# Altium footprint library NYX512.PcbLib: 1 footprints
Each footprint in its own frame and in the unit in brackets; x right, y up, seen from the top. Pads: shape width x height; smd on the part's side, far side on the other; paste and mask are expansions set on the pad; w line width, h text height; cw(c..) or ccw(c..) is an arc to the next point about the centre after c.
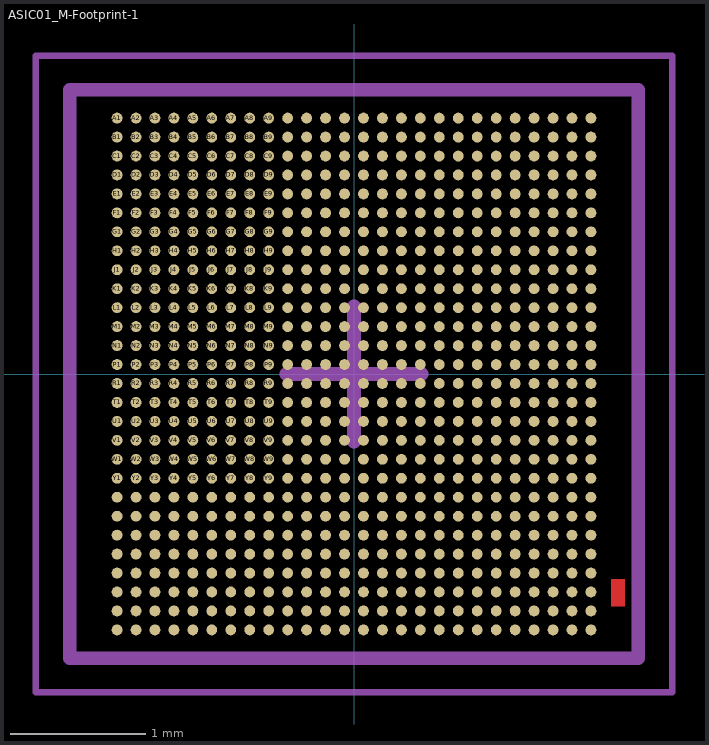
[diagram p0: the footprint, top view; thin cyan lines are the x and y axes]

## ASIC01_M-Footprint-1 [mm]
pads (728):
  round 0.08 smd mask+0: A1(-1.75,1.89) A2(-1.61,1.89) A3(-1.47,1.89) A4(-1.33,1.89) A5(-1.19,1.89) A6(-1.05,1.89) A7(-0.91,1.89) A8(-0.77,1.89) A9(-0.63,1.89) A10(-0.49,1.89) A11(-0.35,1.89) A12(-0.21,1.89) A13(-0.07,1.89) A14(0.07,1.89) A15(0.21,1.89) A16(0.35,1.89) A17(0.49,1.89) A18(0.63,1.89) A19(0.77,1.89) A20(0.91,1.89) A21(1.05,1.89) A22(1.19,1.89) A23(1.33,1.89) A24(1.47,1.89) A25(1.61,1.89) A26(1.75,1.89) AA1(-1.75,-0.91) AA2(-1.61,-0.91) AA3(-1.47,-0.91) AA4(-1.33,-0.91) AA5(-1.19,-0.91) AA6(-1.05,-0.91) AA7(-0.91,-0.91) AA8(-0.77,-0.91) AA9(-0.63,-0.91) AA10(-0.49,-0.91) AA11(-0.35,-0.91) AA12(-0.21,-0.91) AA13(-0.07,-0.91) AA14(0.07,-0.91) AA15(0.21,-0.91) AA16(0.35,-0.91) AA17(0.49,-0.91) AA18(0.63,-0.91) AA19(0.77,-0.91) AA20(0.91,-0.91) AA21(1.05,-0.91) AA22(1.19,-0.91) AA23(1.33,-0.91) AA24(1.47,-0.91) AA25(1.61,-0.91) AA26(1.75,-0.91) AB1(-1.75,-1.05) AB2(-1.61,-1.05) AB3(-1.47,-1.05) AB4(-1.33,-1.05) AB5(-1.19,-1.05) AB6(-1.05,-1.05) AB7(-0.91,-1.05) AB8(-0.77,-1.05) AB9(-0.63,-1.05) AB10(-0.49,-1.05) AB11(-0.35,-1.05) AB12(-0.21,-1.05) AB13(-0.07,-1.05) AB14(0.07,-1.05) AB15(0.21,-1.05) AB16(0.35,-1.05) AB17(0.49,-1.05) AB18(0.63,-1.05) AB19(0.77,-1.05) AB20(0.91,-1.05) AB21(1.05,-1.05) AB22(1.19,-1.05) AB23(1.33,-1.05) AB24(1.47,-1.05) AB25(1.61,-1.05) AB26(1.75,-1.05) AC1(-1.75,-1.19) AC2(-1.61,-1.19) AC3(-1.47,-1.19) AC4(-1.33,-1.19) AC5(-1.19,-1.19) AC6(-1.05,-1.19) AC7(-0.91,-1.19) AC8(-0.77,-1.19) AC9(-0.63,-1.19) AC10(-0.49,-1.19) AC11(-0.35,-1.19) AC12(-0.21,-1.19) AC13(-0.07,-1.19) AC14(0.07,-1.19) AC15(0.21,-1.19) AC16(0.35,-1.19) AC17(0.49,-1.19) AC18(0.63,-1.19) AC19(0.77,-1.19) AC20(0.91,-1.19) AC21(1.05,-1.19) AC22(1.19,-1.19) AC23(1.33,-1.19) AC24(1.47,-1.19) AC25(1.61,-1.19) AC26(1.75,-1.19) AD1(-1.75,-1.33) AD2(-1.61,-1.33) AD3(-1.47,-1.33) AD4(-1.33,-1.33) AD5(-1.19,-1.33) AD6(-1.05,-1.33) AD7(-0.91,-1.33) AD8(-0.77,-1.33) AD9(-0.63,-1.33) AD10(-0.49,-1.33) AD11(-0.35,-1.33) AD12(-0.21,-1.33) AD13(-0.07,-1.33) AD14(0.07,-1.33) AD15(0.21,-1.33) AD16(0.35,-1.33) AD17(0.49,-1.33) AD18(0.63,-1.33) AD19(0.77,-1.33) AD20(0.91,-1.33) AD21(1.05,-1.33) AD22(1.19,-1.33) AD23(1.33,-1.33) AD24(1.47,-1.33) AD25(1.61,-1.33) AD26(1.75,-1.33) AE1(-1.75,-1.47) AE2(-1.61,-1.47) AE3(-1.47,-1.47) AE4(-1.33,-1.47) AE5(-1.19,-1.47) AE6(-1.05,-1.47) AE7(-0.91,-1.47) AE8(-0.77,-1.47) AE9(-0.63,-1.47) AE10(-0.49,-1.47) AE11(-0.35,-1.47) AE12(-0.21,-1.47) AE13(-0.07,-1.47) AE14(0.07,-1.47) AE15(0.21,-1.47) AE16(0.35,-1.47) AE17(0.49,-1.47) AE18(0.63,-1.47) AE19(0.77,-1.47) AE20(0.91,-1.47) AE21(1.05,-1.47) AE22(1.19,-1.47) AE23(1.33,-1.47) AE24(1.47,-1.47) AE25(1.61,-1.47) AE26(1.75,-1.47) AF1(-1.75,-1.61) AF2(-1.61,-1.61) AF3(-1.47,-1.61) AF4(-1.33,-1.61) AF5(-1.19,-1.61) AF6(-1.05,-1.61) AF7(-0.91,-1.61) AF8(-0.77,-1.61) AF9(-0.63,-1.61) AF10(-0.49,-1.61) AF11(-0.35,-1.61) AF12(-0.21,-1.61) AF13(-0.07,-1.61) AF14(0.07,-1.61) AF15(0.21,-1.61) AF16(0.35,-1.61) AF17(0.49,-1.61) AF18(0.63,-1.61) AF19(0.77,-1.61) AF20(0.91,-1.61) AF21(1.05,-1.61) AF22(1.19,-1.61) AF23(1.33,-1.61) AF24(1.47,-1.61) AF25(1.61,-1.61) AF26(1.75,-1.61) AG1(-1.75,-1.75) AG2(-1.61,-1.75) AG3(-1.47,-1.75) AG4(-1.33,-1.75) AG5(-1.19,-1.75) AG6(-1.05,-1.75) AG7(-0.91,-1.75) AG8(-0.77,-1.75) AG9(-0.63,-1.75) AG10(-0.49,-1.75) AG11(-0.35,-1.75) AG12(-0.21,-1.75) AG13(-0.07,-1.75) AG14(0.07,-1.75) AG15(0.21,-1.75) AG16(0.35,-1.75) AG17(0.49,-1.75) AG18(0.63,-1.75) AG19(0.77,-1.75) AG20(0.91,-1.75) AG21(1.05,-1.75) AG22(1.19,-1.75) AG23(1.33,-1.75) AG24(1.47,-1.75) AG25(1.61,-1.75) AG26(1.75,-1.75) AH1(-1.75,-1.89) AH2(-1.61,-1.89) AH3(-1.47,-1.89) AH4(-1.33,-1.89) AH5(-1.19,-1.89) AH6(-1.05,-1.89) AH7(-0.91,-1.89) AH8(-0.77,-1.89) AH9(-0.63,-1.89) AH10(-0.49,-1.89) AH11(-0.35,-1.89) AH12(-0.21,-1.89) AH13(-0.07,-1.89) AH14(0.07,-1.89) AH15(0.21,-1.89) AH16(0.35,-1.89) AH17(0.49,-1.89) AH18(0.63,-1.89) AH19(0.77,-1.89) AH20(0.91,-1.89) AH21(1.05,-1.89) AH22(1.19,-1.89) AH23(1.33,-1.89) AH24(1.47,-1.89) AH25(1.61,-1.89) AH26(1.75,-1.89) B1(-1.75,1.75) B2(-1.61,1.75) B3(-1.47,1.75) B4(-1.33,1.75) B5(-1.19,1.75) B6(-1.05,1.75) B7(-0.91,1.75) B8(-0.77,1.75) B9(-0.63,1.75) B10(-0.49,1.75) B11(-0.35,1.75) B12(-0.21,1.75) B13(-0.07,1.75) B14(0.07,1.75) B15(0.21,1.75) B16(0.35,1.75) B17(0.49,1.75) B18(0.63,1.75) B19(0.77,1.75) B20(0.91,1.75) B21(1.05,1.75) B22(1.19,1.75) B23(1.33,1.75) B24(1.47,1.75) B25(1.61,1.75) B26(1.75,1.75) C1(-1.75,1.61) C2(-1.61,1.61) C3(-1.47,1.61) C4(-1.33,1.61) C5(-1.19,1.61) C6(-1.05,1.61) C7(-0.91,1.61) C8(-0.77,1.61) C9(-0.63,1.61) C10(-0.49,1.61) C11(-0.35,1.61) C12(-0.21,1.61) C13(-0.07,1.61) C14(0.07,1.61) C15(0.21,1.61) C16(0.35,1.61) C17(0.49,1.61) C18(0.63,1.61) C19(0.77,1.61) C20(0.91,1.61) C21(1.05,1.61) C22(1.19,1.61) C23(1.33,1.61) C24(1.47,1.61) C25(1.61,1.61) C26(1.75,1.61) D1(-1.75,1.47) D2(-1.61,1.47) D3(-1.47,1.47) D4(-1.33,1.47) D5(-1.19,1.47) D6(-1.05,1.47) D7(-0.91,1.47) D8(-0.77,1.47) D9(-0.63,1.47) D10(-0.49,1.47) D11(-0.35,1.47) D12(-0.21,1.47) D13(-0.07,1.47) D14(0.07,1.47) D15(0.21,1.47) D16(0.35,1.47) D17(0.49,1.47) D18(0.63,1.47) D19(0.77,1.47) D20(0.91,1.47) D21(1.05,1.47) D22(1.19,1.47) D23(1.33,1.47) D24(1.47,1.47) D25(1.61,1.47) D26(1.75,1.47) E1(-1.75,1.33) E2(-1.61,1.33) E3(-1.47,1.33) E4(-1.33,1.33) E5(-1.19,1.33) E6(-1.05,1.33) E7(-0.91,1.33) E8(-0.77,1.33) E9(-0.63,1.33) E10(-0.49,1.33) E11(-0.35,1.33) E12(-0.21,1.33) E13(-0.07,1.33) E14(0.07,1.33) E15(0.21,1.33) E16(0.35,1.33) E17(0.49,1.33) E18(0.63,1.33) E19(0.77,1.33) E20(0.91,1.33) E21(1.05,1.33) E22(1.19,1.33) E23(1.33,1.33) E24(1.47,1.33) E25(1.61,1.33) E26(1.75,1.33) F1(-1.75,1.19) F2(-1.61,1.19) F3(-1.47,1.19) F4(-1.33,1.19) F5(-1.19,1.19) F6(-1.05,1.19) F7(-0.91,1.19) F8(-0.77,1.19) F9(-0.63,1.19) F10(-0.49,1.19) F11(-0.35,1.19) F12(-0.21,1.19) F13(-0.07,1.19) F14(0.07,1.19) F15(0.21,1.19) F16(0.35,1.19) F17(0.49,1.19) F18(0.63,1.19) F19(0.77,1.19) F20(0.91,1.19) F21(1.05,1.19) F22(1.19,1.19) F23(1.33,1.19) F24(1.47,1.19) F25(1.61,1.19) F26(1.75,1.19) G1(-1.75,1.05) G2(-1.61,1.05) G3(-1.47,1.05) G4(-1.33,1.05) G5(-1.19,1.05) G6(-1.05,1.05) G7(-0.91,1.05) G8(-0.77,1.05) G9(-0.63,1.05) G10(-0.49,1.05) G11(-0.35,1.05) G12(-0.21,1.05) G13(-0.07,1.05) G14(0.07,1.05) G15(0.21,1.05) G16(0.35,1.05) G17(0.49,1.05) G18(0.63,1.05) G19(0.77,1.05) G20(0.91,1.05) G21(1.05,1.05) G22(1.19,1.05) G23(1.33,1.05) G24(1.47,1.05) G25(1.61,1.05) G26(1.75,1.05) H1(-1.75,0.91) H2(-1.61,0.91) H3(-1.47,0.91) H4(-1.33,0.91) H5(-1.19,0.91) H6(-1.05,0.91) H7(-0.91,0.91) H8(-0.77,0.91) H9(-0.63,0.91) H10(-0.49,0.91) H11(-0.35,0.91) H12(-0.21,0.91) H13(-0.07,0.91) H14(0.07,0.91) H15(0.21,0.91) H16(0.35,0.91) H17(0.49,0.91) H18(0.63,0.91) H19(0.77,0.91) H20(0.91,0.91) H21(1.05,0.91) H22(1.19,0.91) H23(1.33,0.91) H24(1.47,0.91) H25(1.61,0.91) H26(1.75,0.91) J1(-1.75,0.77) J2(-1.61,0.77) J3(-1.47,0.77) J4(-1.33,0.77) J5(-1.19,0.77) J6(-1.05,0.77) J7(-0.91,0.77) J8(-0.77,0.77) J9(-0.63,0.77) J10(-0.49,0.77) J11(-0.35,0.77) J12(-0.21,0.77) J13(-0.07,0.77) J14(0.07,0.77) J15(0.21,0.77) J16(0.35,0.77) J17(0.49,0.77) J18(0.63,0.77) J19(0.77,0.77) J20(0.91,0.77) J21(1.05,0.77) J22(1.19,0.77) J23(1.33,0.77) J24(1.47,0.77) J25(1.61,0.77) J26(1.75,0.77) K1(-1.75,0.63) K2(-1.61,0.63) K3(-1.47,0.63) K4(-1.33,0.63) K5(-1.19,0.63) K6(-1.05,0.63) K7(-0.91,0.63) K8(-0.77,0.63) K9(-0.63,0.63) K10(-0.49,0.63) K11(-0.35,0.63) K12(-0.21,0.63) K13(-0.07,0.63) K14(0.07,0.63) K15(0.21,0.63) K16(0.35,0.63) K17(0.49,0.63) K18(0.63,0.63) K19(0.77,0.63) K20(0.91,0.63) K21(1.05,0.63) K22(1.19,0.63) K23(1.33,0.63) K24(1.47,0.63) K25(1.61,0.63) K26(1.75,0.63) L1(-1.75,0.49) L2(-1.61,0.49) L3(-1.47,0.49) L4(-1.33,0.49) L5(-1.19,0.49) L6(-1.05,0.49) L7(-0.91,0.49) L8(-0.77,0.49) L9(-0.63,0.49) L10(-0.49,0.49) L11(-0.35,0.49) L12(-0.21,0.49) L13(-0.07,0.49) L14(0.07,0.49) L15(0.21,0.49) L16(0.35,0.49) L17(0.49,0.49) L18(0.63,0.49) L19(0.77,0.49) L20(0.91,0.49) L21(1.05,0.49) L22(1.19,0.49) L23(1.33,0.49) L24(1.47,0.49) L25(1.61,0.49) L26(1.75,0.49) M1(-1.75,0.35) M2(-1.61,0.35) M3(-1.47,0.35) M4(-1.33,0.35) M5(-1.19,0.35) M6(-1.05,0.35) M7(-0.91,0.35) M8(-0.77,0.35) M9(-0.63,0.35) M10(-0.49,0.35) M11(-0.35,0.35) M12(-0.21,0.35) M13(-0.07,0.35) M14(0.07,0.35) M15(0.21,0.35) M16(0.35,0.35) M17(0.49,0.35) M18(0.63,0.35) M19(0.77,0.35) M20(0.91,0.35) M21(1.05,0.35) M22(1.19,0.35) M23(1.33,0.35) M24(1.47,0.35) M25(1.61,0.35) M26(1.75,0.35) N1(-1.75,0.21) N2(-1.61,0.21) N3(-1.47,0.21) N4(-1.33,0.21) N5(-1.19,0.21) N6(-1.05,0.21) N7(-0.91,0.21) N8(-0.77,0.21) N9(-0.63,0.21) N10(-0.49,0.21) N11(-0.35,0.21) N12(-0.21,0.21) N13(-0.07,0.21) N14(0.07,0.21) N15(0.21,0.21) N16(0.35,0.21) N17(0.49,0.21) N18(0.63,0.21) N19(0.77,0.21) N20(0.91,0.21) N21(1.05,0.21) N22(1.19,0.21) N23(1.33,0.21) N24(1.47,0.21) N25(1.61,0.21) N26(1.75,0.21) P1(-1.75,0.07) P2(-1.61,0.07) P3(-1.47,0.07) P4(-1.33,0.07) P5(-1.19,0.07) P6(-1.05,0.07) P7(-0.91,0.07) P8(-0.77,0.07) P9(-0.63,0.07) P10(-0.49,0.07) P11(-0.35,0.07) P12(-0.21,0.07) P13(-0.07,0.07) P14(0.07,0.07) P15(0.21,0.07) P16(0.35,0.07) P17(0.49,0.07) P18(0.63,0.07) P19(0.77,0.07) P20(0.91,0.07) P21(1.05,0.07) P22(1.19,0.07) P23(1.33,0.07) P24(1.47,0.07) P25(1.61,0.07) P26(1.75,0.07) R1(-1.75,-0.07) R2(-1.61,-0.07) R3(-1.47,-0.07) R4(-1.33,-0.07) R5(-1.19,-0.07) R6(-1.05,-0.07) R7(-0.91,-0.07) R8(-0.77,-0.07) R9(-0.63,-0.07) R10(-0.49,-0.07) R11(-0.35,-0.07) R12(-0.21,-0.07) R13(-0.07,-0.07) R14(0.07,-0.07) R15(0.21,-0.07) R16(0.35,-0.07) R17(0.49,-0.07) R18(0.63,-0.07) R19(0.77,-0.07) R20(0.91,-0.07) R21(1.05,-0.07) R22(1.19,-0.07) R23(1.33,-0.07) R24(1.47,-0.07) R25(1.61,-0.07) R26(1.75,-0.07) T1(-1.75,-0.21) T2(-1.61,-0.21) T3(-1.47,-0.21) T4(-1.33,-0.21) T5(-1.19,-0.21) T6(-1.05,-0.21) T7(-0.91,-0.21) T8(-0.77,-0.21) T9(-0.63,-0.21) T10(-0.49,-0.21) T11(-0.35,-0.21) T12(-0.21,-0.21) T13(-0.07,-0.21) T14(0.07,-0.21) T15(0.21,-0.21) T16(0.35,-0.21) T17(0.49,-0.21) T18(0.63,-0.21) T19(0.77,-0.21) T20(0.91,-0.21) T21(1.05,-0.21) T22(1.19,-0.21) T23(1.33,-0.21) T24(1.47,-0.21) T25(1.61,-0.21) T26(1.75,-0.21) U1(-1.75,-0.35) U2(-1.61,-0.35) U3(-1.47,-0.35) U4(-1.33,-0.35) U5(-1.19,-0.35) U6(-1.05,-0.35) U7(-0.91,-0.35) U8(-0.77,-0.35) U9(-0.63,-0.35) U10(-0.49,-0.35) U11(-0.35,-0.35) U12(-0.21,-0.35) U13(-0.07,-0.35) U14(0.07,-0.35) U15(0.21,-0.35) U16(0.35,-0.35) U17(0.49,-0.35) U18(0.63,-0.35) U19(0.77,-0.35) U20(0.91,-0.35) U21(1.05,-0.35) U22(1.19,-0.35) U23(1.33,-0.35) U24(1.47,-0.35) U25(1.61,-0.35) U26(1.75,-0.35) V1(-1.75,-0.49) V2(-1.61,-0.49) V3(-1.47,-0.49) V4(-1.33,-0.49) V5(-1.19,-0.49) V6(-1.05,-0.49) V7(-0.91,-0.49) V8(-0.77,-0.49) V9(-0.63,-0.49) V10(-0.49,-0.49) V11(-0.35,-0.49) V12(-0.21,-0.49) V13(-0.07,-0.49) V14(0.07,-0.49) V15(0.21,-0.49) V16(0.35,-0.49) V17(0.49,-0.49) V18(0.63,-0.49) V19(0.77,-0.49) V20(0.91,-0.49) V21(1.05,-0.49) V22(1.19,-0.49) V23(1.33,-0.49) V24(1.47,-0.49) V25(1.61,-0.49) V26(1.75,-0.49) W1(-1.75,-0.63) W2(-1.61,-0.63) W3(-1.47,-0.63) W4(-1.33,-0.63) W5(-1.19,-0.63) W6(-1.05,-0.63) W7(-0.91,-0.63) W8(-0.77,-0.63) W9(-0.63,-0.63) W10(-0.49,-0.63) W11(-0.35,-0.63) W12(-0.21,-0.63) W13(-0.07,-0.63) W14(0.07,-0.63) W15(0.21,-0.63) W16(0.35,-0.63) W17(0.49,-0.63) W18(0.63,-0.63) W19(0.77,-0.63) W20(0.91,-0.63) W21(1.05,-0.63) W22(1.19,-0.63) W23(1.33,-0.63) W24(1.47,-0.63) W25(1.61,-0.63) W26(1.75,-0.63) Y1(-1.75,-0.77) Y2(-1.61,-0.77) Y3(-1.47,-0.77) Y4(-1.33,-0.77) Y5(-1.19,-0.77) Y6(-1.05,-0.77) Y7(-0.91,-0.77) Y8(-0.77,-0.77) Y9(-0.63,-0.77) Y10(-0.49,-0.77) Y11(-0.35,-0.77) Y12(-0.21,-0.77) Y13(-0.07,-0.77) Y14(0.07,-0.77) Y15(0.21,-0.77) Y16(0.35,-0.77) Y17(0.49,-0.77) Y18(0.63,-0.77) Y19(0.77,-0.77) Y20(0.91,-0.77) Y21(1.05,-0.77) Y22(1.19,-0.77) Y23(1.33,-0.77) Y24(1.47,-0.77) Y25(1.61,-0.77) Y26(1.75,-0.77)
Top Layer:
  region: 1.899,-1.515 1.999,-1.515 1.999,-1.715 1.899,-1.715
Mechanical 13:
  lines w0.1: -2.1,-2.1 -2.1,2.1 2.1,2.1 2.1,-2.1 -2.1,-2.1
Mechanical 15:
  lines w0.05: -2.35,-2.35 -2.35,2.35 2.35,2.35 2.35,-2.35 -2.35,-2.35
  lines w0.1: -0.5,0 0.5,0 ; 0,-0.5 0,0.5
3D body: height 0.15, standoff 0, extent -2.1,-2.1 2.1,2.1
